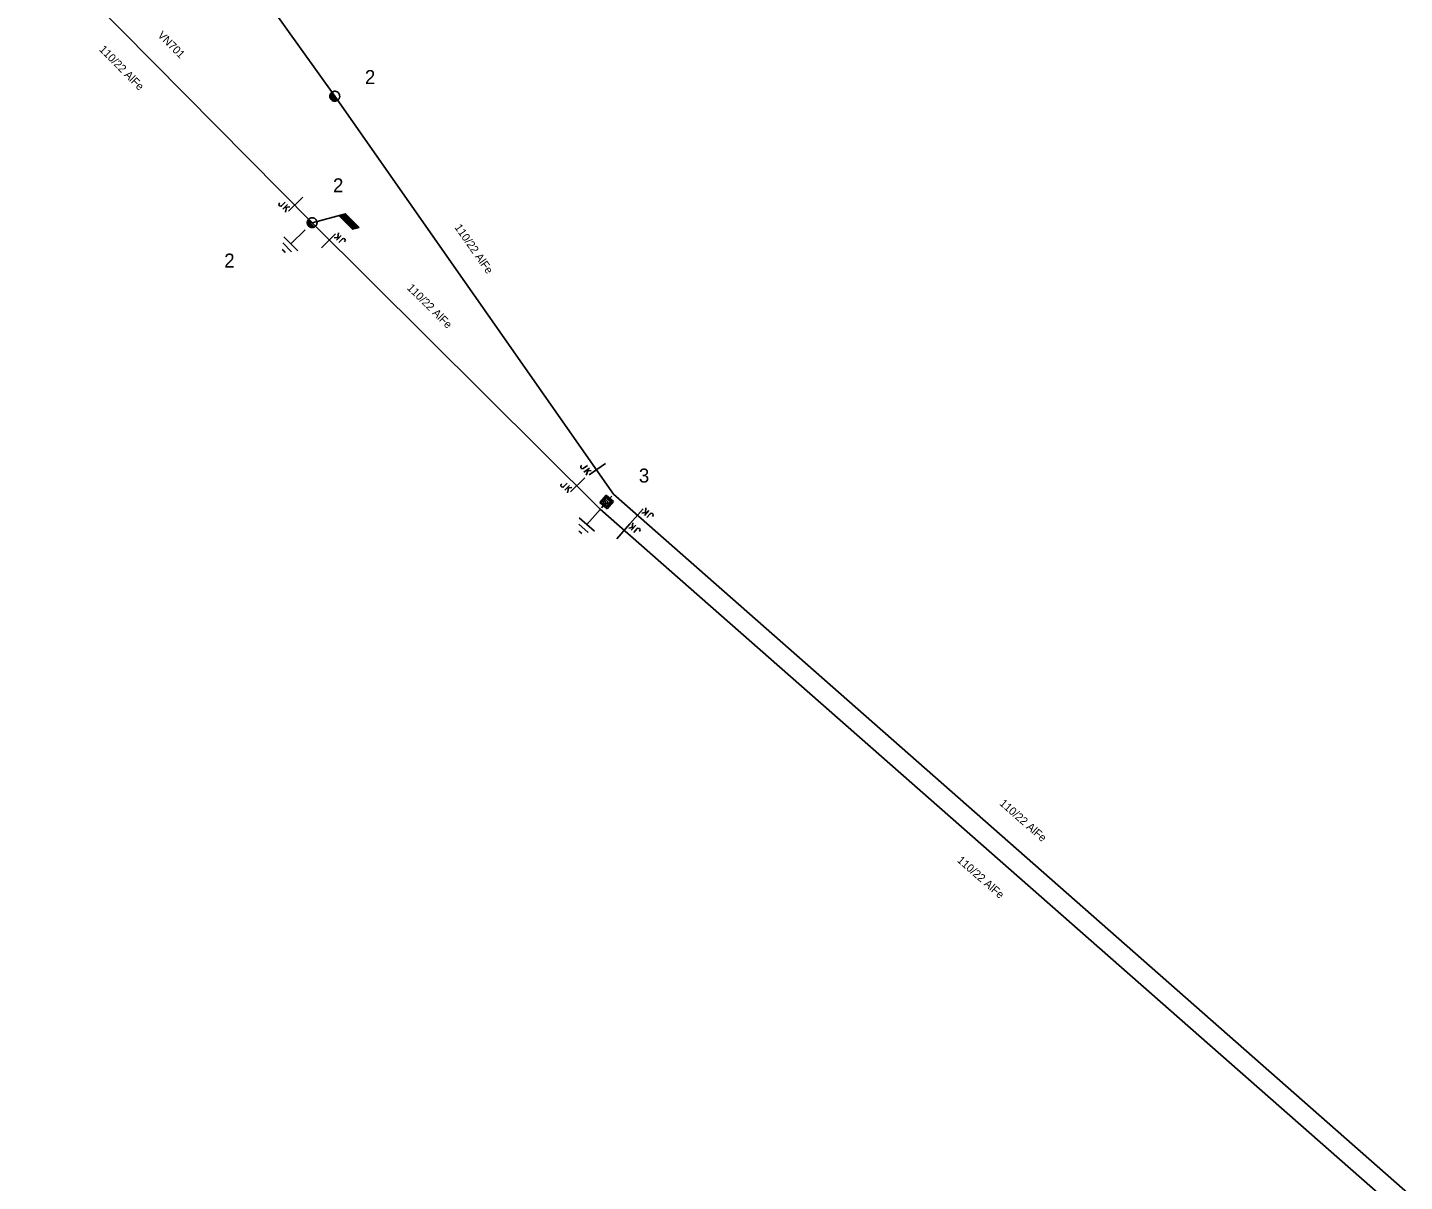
# Model space of a CAD drawing. Extents: x -545588 to -543214, y -1196037 to -1194452.
# Drawn here: x -545161.2 to -544989.1, y -1195049.9 to -1194905.8 of the extents above; entities that cross this region are included whole.
import ezdxf

# ---------------------------------------------------------------- set-up
doc = ezdxf.new("R2010")
doc.units = 0
for name, color, linetype in [('Default', 7, 'Continuous'), ('Vrstva 1', 7, 'Continuous'), ('Vrstva 11', 7, 'Continuous'), ('Vrstva 12', 7, 'Continuous'), ('Vrstva 13', 7, 'Continuous'), ('Vrstva 14', 7, 'Continuous'), ('Vrstva 15', 7, 'Continuous'), ('Vrstva 18', 7, 'Continuous'), ('Vrstva 2', 7, 'Continuous'), ('Vrstva 3', 7, 'Continuous')]:
    doc.layers.add(name, color=color, linetype=linetype)

# ---------------------------------------------------------------- blocks, each defined once
blk = doc.blocks.new('VN840')
at = {"layer": 'Vrstva 15'}
for points in [[(-0.01, 1.41), (-0.01, -1.09)], [(-1.51, -1.24), (-1.51, -1.15)], [(-1.48, -1.35), (-1.51, -1.24)], [(-1.33, -1.42), (-1.48, -1.35)], [(-1.27, -1.42), (-1.33, -1.42)], [(-1.13, -1.35), (-1.27, -1.42)], [(-1.09, -1.24), (-1.13, -1.35)], [(-1.09, -0.59), (-1.09, -1.24)], [(-0.68, -0.59), (-0.68, -1.42)], [(-0.68, -1.11), (-0.27, -0.59)], [(-0.54, -0.94), (-0.2, -1.42)]]:
    blk.add_lwpolyline(points, dxfattribs=at)
blk = doc.blocks.new('VN440')
at = {"layer": 'Vrstva 2'}
for points in [[(1.22, 0), (1.21, 0.13), (1.19, 0.25), (1.16, 0.38), (1.11, 0.5), (1.05, 0.61), (0.98, 0.72), (0.9, 0.82), (0.81, 0.91), (0.71, 0.99), (0.6, 1.06), (0.49, 1.12), (0.37, 1.16), (0.25, 1.2), (0.12, 1.22), (-0.01, 1.22), (-0.14, 1.22), (-0.26, 1.2), (-0.39, 1.16), (-0.51, 1.12), (-0.62, 1.06), (-0.73, 0.99), (-0.83, 0.91), (-0.92, 0.82), (-1, 0.72), (-1.07, 0.61), (-1.13, 0.5), (-1.18, 0.38), (-1.21, 0.25), (-1.23, 0.13), (-1.24, 0), (-1.23, -0.13), (-1.21, -0.26), (-1.18, -0.38), (-1.13, -0.5), (-1.07, -0.62), (-1, -0.73), (-0.92, -0.83), (-0.83, -0.92), (-0.73, -1), (-0.62, -1.07), (-0.51, -1.13), (-0.39, -1.17), (-0.26, -1.2), (-0.14, -1.23), (-0.01, -1.23), (0.12, -1.23), (0.25, -1.2), (0.37, -1.17), (0.49, -1.13), (0.6, -1.07), (0.71, -1), (0.81, -0.92), (0.9, -0.83), (0.98, -0.73), (1.05, -0.62), (1.11, -0.5), (1.16, -0.38), (1.19, -0.26), (1.21, -0.13), (1.22, 0)], [(-1.24, 0), (1.22, 0)], [(-1.18, -0.34), (1.1, -0.34)], [(-1.01, -0.63), (0.97, -0.63)], [(-0.74, -0.92), (0.68, -0.92)]]:
    blk.add_lwpolyline(points, dxfattribs=at)
blk = doc.blocks.new('VN810')
at = {"layer": 'Vrstva 14'}
for points in [[(0, -1.25), (0, -3.75)], [(1.25, -3.75), (-1.25, -3.75)], [(0.77, -4.37), (-0.8, -4.37)], [(0, -5), (-0.25, -5)], [(0.27, -5), (0, -5)]]:
    blk.add_lwpolyline(points, dxfattribs=at)
blk = doc.blocks.new('VN001')
at = {"layer": 'Default'}
for p, q in [((1.99, 3.48), (4.4, 3.48)), ((2.02, 3.53), (4.43, 3.53)), ((2.05, 3.58), (4.46, 3.58)), ((2.07, 3.63), (4.49, 3.63)), ((2.1, 3.68), (4.52, 3.68)), ((2.13, 3.73), (2.54, 3.73)), ((1.73, 3.03), (4.14, 3.03)), ((1.76, 3.08), (4.17, 3.08)), ((1.79, 3.13), (4.2, 3.13)), ((1.82, 3.18), (4.23, 3.18)), ((1.85, 3.23), (4.26, 3.23)), ((1.87, 3.28), (4.29, 3.28)), ((1.9, 3.33), (4.32, 3.33)), ((1.93, 3.38), (4.35, 3.38)), ((1.96, 3.43), (4.37, 3.43))]:
    blk.add_line(p, q, dxfattribs=at)
blk.add_lwpolyline([(2.13, 3.73), (0, 0)], dxfattribs=at)
blk.add_lwpolyline([(4.55, 3.73), (2.13, 3.73), (1.7, 2.98), (4.12, 2.99)], close=True, dxfattribs=at)
blk = doc.blocks.new('VN470')
at = {"layer": 'Vrstva 2'}
for points in [[(-1.23, 1.22), (1.23, 1.22)], [(-1.23, -1.23), (-1.23, 1.22)], [(-0.92, 0.9), (0.92, 0.9)], [(-0.92, -0.95), (-0.92, 0.9)], [(-0.61, 0.61), (0.61, 0.61)], [(-0.61, -0.62), (-0.61, 0.61)], [(-0.31, -0.27), (-0.31, 0.34)], [(-0.31, 0.34), (0.31, 0.34)], [(0, 1.22), (0, 1.97)], [(0.31, 0.34), (0.31, -0.27)], [(0.61, 0.61), (0.61, -0.62)], [(0.92, 0.9), (0.92, -0.95)], [(1.23, 1.22), (1.23, -1.23)], [(1.23, -1.23), (-1.23, -1.23)], [(0.92, -0.95), (-0.92, -0.95)], [(0.61, -0.62), (-0.61, -0.62)], [(0.31, -0.27), (-0.31, -0.27)], [(0, -1.23), (0, -1.98)]]:
    blk.add_lwpolyline(points, dxfattribs=at)

msp = doc.modelspace()

# ---------------------------------------------------------------- linework, layer by layer
at = {"layer": 'Vrstva 1'}
for points in [[(-545145.32, -1194882.87), (-545144.58, -1194883.9), (-545122.79, -1194914.35), (-545087.98, -1194964.09)], [(-545125.62, -1194930.15), (-545157.44, -1194897.99), (-545161.19, -1194894.21)], [(-545089.61, -1194965.95), (-545125.62, -1194930.15)], [(-545087.98, -1194964.09), (-544969.35, -1195068.41), (-544833.03, -1195149.76), (-544688.41, -1195235.46), (-544556.36, -1195314.32), (-544420.24, -1195394.62), (-544279.84, -1195477.88), (-544141.02, -1195559.94), (-544005.67, -1195639.57), (-543873.94, -1195717.89), (-543750.35, -1195790.92), (-543648.17, -1195852.31)], [(-543649.39, -1195854.44), (-543751.62, -1195793.1), (-543875.2, -1195719.97), (-544006.92, -1195641.71), (-544142.24, -1195562.12), (-544281.11, -1195480), (-544421.5, -1195396.73), (-544557.6, -1195316.44), (-544689.64, -1195237.57), (-544834.28, -1195151.89), (-544970.6, -1195070.55), (-545089.61, -1194965.95)]]:
    msp.add_lwpolyline(points, dxfattribs=at)

# ---------------------------------------------------------------- block references
at = {"layer": 'Vrstva 11', "rotation": -45.29673610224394}
msp.add_blockref('VN001', (-545125.62, -1194930.15), dxfattribs=at)
at = {"layer": 'Vrstva 13'}
for name, p, xscale, yscale, rotation in [('VN440', (-545122.79, -1194914.35), 0.49999999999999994, 0.5000000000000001, -54.40895272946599), ('VN440', (-545125.62, -1194930.15), 0.5, 0.5, -45.2964556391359), ('VN470', (-545088.82, -1194965.05), 0.5000000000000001, 0.5, 138.68979446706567)]:
    msp.add_blockref(name, p, dxfattribs=dict(at, xscale=xscale, yscale=yscale, rotation=rotation))
at = {"layer": 'Vrstva 15'}
for p, rotation in [((-545125.62, -1194930.15), -45.29695556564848), ((-545088.82, -1194965.05), -41.310969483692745)]:
    msp.add_blockref('VN810', p, dxfattribs=dict(at, rotation=rotation))
at = {"layer": 'Vrstva 18'}
for p, rotation in [((-545127.79, -1194927.96), -45.29645278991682), ((-545123.47, -1194932.29), 135.1667500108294), ((-545090.11, -1194961.05), -55.01524725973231), ((-545092.55, -1194963.03), -44.83325003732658), ((-545085, -1194966.72), 138.67199996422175), ((-545086.64, -1194968.57), 138.68738612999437)]:
    msp.add_blockref('VN840', p, dxfattribs=dict(at, rotation=rotation))

# ---------------------------------------------------------------- texts
at = {"layer": 'Vrstva 12'}
msp.add_text('2', height=1.75, dxfattribs=at).set_placement((-545136.61, -1194935.76))
at = {"layer": 'Vrstva 14'}
for s, p in [('2', (-545119.03, -1194912.83)), ('2', (-545123.02, -1194926.36)), ('3', (-545084.8, -1194962.62))]:
    msp.add_text(s, height=1.75, dxfattribs=at).set_placement(p)
at = {"layer": 'Vrstva 2'}
for rotation, p in [(314.704, (-545152.31, -1194908.58)), (304.985, (-545107.88, -1194930.74)), (315.167, (-545113.84, -1194938.37)), (318.672, (-545039.8, -1195002.82)), (318.687, (-545045.1, -1195009.93))]:
    msp.add_text('110/22 AlFe', height=1, rotation=rotation, dxfattribs=at).set_placement(p)
at = {"layer": 'Vrstva 3'}
msp.add_text('VN701', height=1, rotation=314.704, dxfattribs=at).set_placement((-545145, -1194906.8))

doc.saveas('drawing.dxf')
